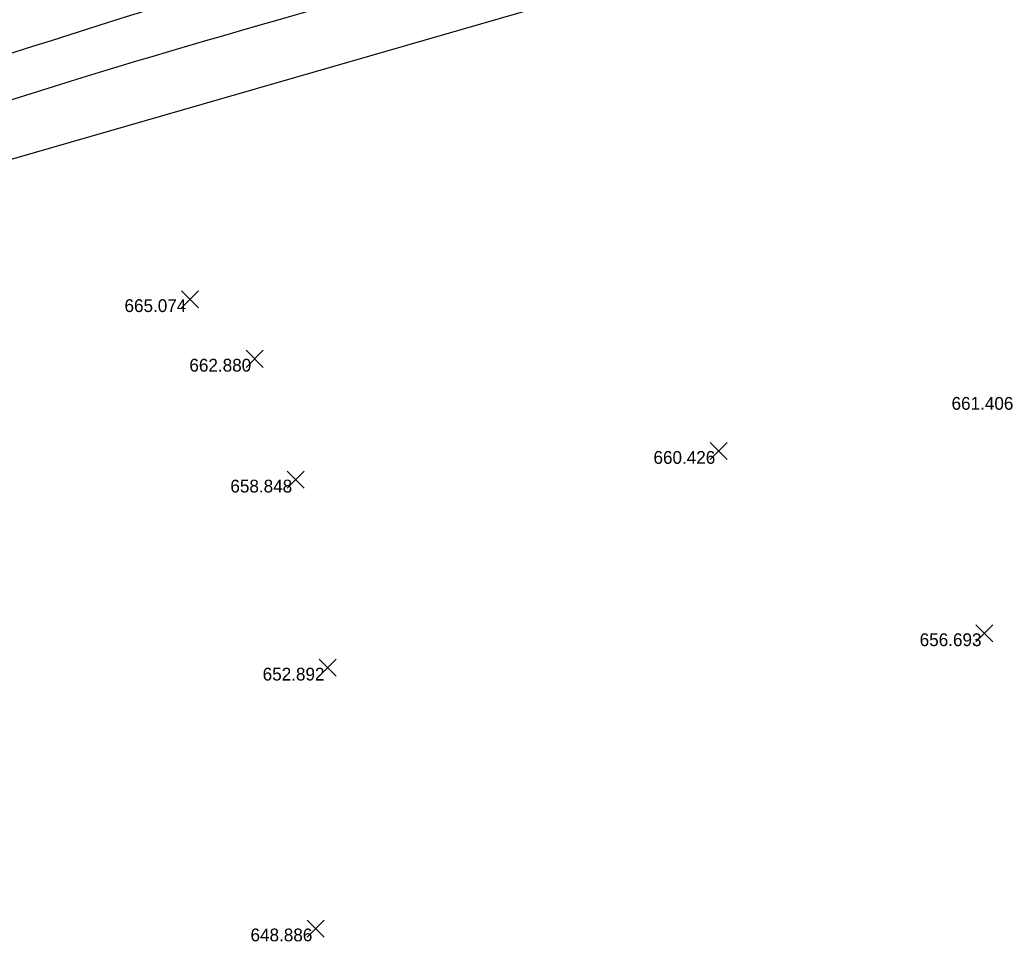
# Model space of a CAD drawing. Extents: x 2197382 to 2204062, y 634117 to 636522.
# Drawn here: x 2203079.3 to 2203155.5, y 635369.8 to 635441.9 of the extents above; entities that cross this region are included whole.
import ezdxf

# ---------------------------------------------------------------- set-up
doc = ezdxf.new("R2010")
doc.units = 0
for name, color, linetype in [('GE_P_Alignment_100_Distances', 7, 'Continuous'), ('GE_X_Alignment', 7, 'Continuous'), ('PF_P_Grade_Line', 7, 'Continuous'), ('RD_X_GR_Rt', 7, 'Continuous'), ('RW_X_CL_100_Curve_Data', 7, 'Continuous'), ('SH_Data', 7, 'Continuous')]:
    doc.layers.add(name, color=color, linetype=linetype)

msp = doc.modelspace()

# ---------------------------------------------------------------- linework, layer by layer
at = {"layer": 'GE_P_Alignment_100_Distances'}
for points in [[(2203509.325, 635523.639), (2203492.709, 635523.635), (2203459.449, 635522.771), (2203409.618, 635520.273), (2203359.906, 635516.085), (2203310.487, 635509.396), (2203261.113, 635501.99), (2203212.046, 635492.428), (2203163.488, 635480.651), (2203115.287, 635467.725), (2203067.636, 635452.84), (2203020.399, 635437.148), (2202989.518, 635425.126), (2202974.268, 635418.841)], [(2203026.75, 635422.164), (2203041.875, 635427.739), (2203072.979, 635437.38), (2203119.81, 635452.49), (2203167.644, 635464.687), (2203215.6, 635476.186), (2203263.862, 635485.772), (2203312.689, 635493.217), (2203361.79, 635499.124), (2203411.114, 635503.522), (2203460.348, 635505.942), (2203493.138, 635506.785), (2203509.372, 635506.858)]]:
    msp.add_open_spline(points, degree=3, dxfattribs=at)
at = {"layer": 'GE_X_Alignment'}
for points in [[(2203509.052, 635533.635), (2203492.463, 635533.632), (2203459.115, 635532.727), (2203409.096, 635530.449), (2203358.983, 635525.688), (2203309.163, 635519.456), (2203259.639, 635511.376), (2203210.257, 635501.873), (2203160.945, 635490.686), (2203112.434, 635476.962), (2203063.465, 635464.847), (2203018.457, 635445.242), (2202987.961, 635434.054), (2202973.986, 635427.145)], [(2203012.655, 635413.013), (2203017.915, 635415.429), (2203038.998, 635420.898), (2203074.314, 635435.088), (2203121.354, 635447.886), (2203168.652, 635461.375), (2203216.374, 635472.836), (2203264.58, 635481.881), (2203313.279, 635489.496), (2203362.166, 635495.909), (2203411.483, 635500.018), (2203460.323, 635502.299), (2203492.764, 635503.649), (2203508.722, 635503.638)]]:
    msp.add_open_spline(points, degree=3, dxfattribs=at)
at = {"layer": 'PF_P_Grade_Line'}
msp.add_lwpolyline([(2203043.467, 635419.844), (2203073.568, 635429.525), (2203121.13, 635443.225), (2203169.12, 635455.802), (2203217.357, 635467.564), (2203230.845, 635471.04), (2203265.329, 635478.99), (2203314.754, 635483.372), (2203364.466, 635491.566), (2203411.447, 635493.017), (2203461.51, 635493.069), (2203507.424, 635496.532), (2203559.602, 635497.109), (2203609.334, 635499.705), (2203659.056, 635500.519), (2203709.247, 635500.733), (2203757.564, 635500.458), (2203810.237, 635498.931), (2203858.686, 635500.086), (2203907.877, 635499.67), (2203958.733, 635497.987), (2204007.218, 635491.867), (2204054.413, 635491.827)], dxfattribs=at)
at = {"layer": 'RD_X_GR_Rt'}
msp.add_open_spline([(2203111.903, 635478.773), (2203095.805, 635474.299), (2203063.972, 635464.196), (2203027.87, 635451.622), (2203008.766, 635441.935), (2203004.506, 635440.095)], degree=3, dxfattribs=at)
at = {"layer": 'RW_X_CL_100_Curve_Data'}
for p, q in [((2203091.939, 635419.346), (2203093.273, 635420.681)), ((2203091.939, 635420.681), (2203093.273, 635419.346)), ((2203097.005, 635414.686), (2203098.339, 635416.022)), ((2203097.005, 635416.022), (2203098.339, 635414.686)), ((2203133.287, 635407.471), (2203134.621, 635408.806)), ((2203133.287, 635408.806), (2203134.621, 635407.471)), ((2203100.196, 635405.228), (2203101.53, 635406.563)), ((2203100.196, 635406.563), (2203101.53, 635405.228)), ((2203154.067, 635393.211), (2203155.401, 635394.546)), ((2203154.067, 635394.546), (2203155.401, 635393.211)), ((2203102.695, 635390.519), (2203104.029, 635391.855)), ((2203102.695, 635391.855), (2203104.029, 635390.519)), ((2203101.775, 635370.117), (2203103.109, 635371.451)), ((2203101.775, 635371.451), (2203103.109, 635370.117))]:
    msp.add_line(p, q, dxfattribs=at)

# ---------------------------------------------------------------- texts
at = {"layer": 'SH_Data'}
for s, p in [('665.074', (2203087.484, 635419.014)), ('662.880', (2203092.558, 635414.354)), ('661.406', (2203152.162, 635411.368)), ('660.426', (2203128.85, 635407.139)), ('658.848', (2203095.763, 635404.896)), ('656.693', (2203149.67, 635392.879)), ('652.892', (2203098.289, 635390.187)), ('648.886', (2203097.338, 635369.784))]:
    msp.add_text(s, height=1, dxfattribs=at).set_placement(p)

doc.saveas('drawing.dxf')
